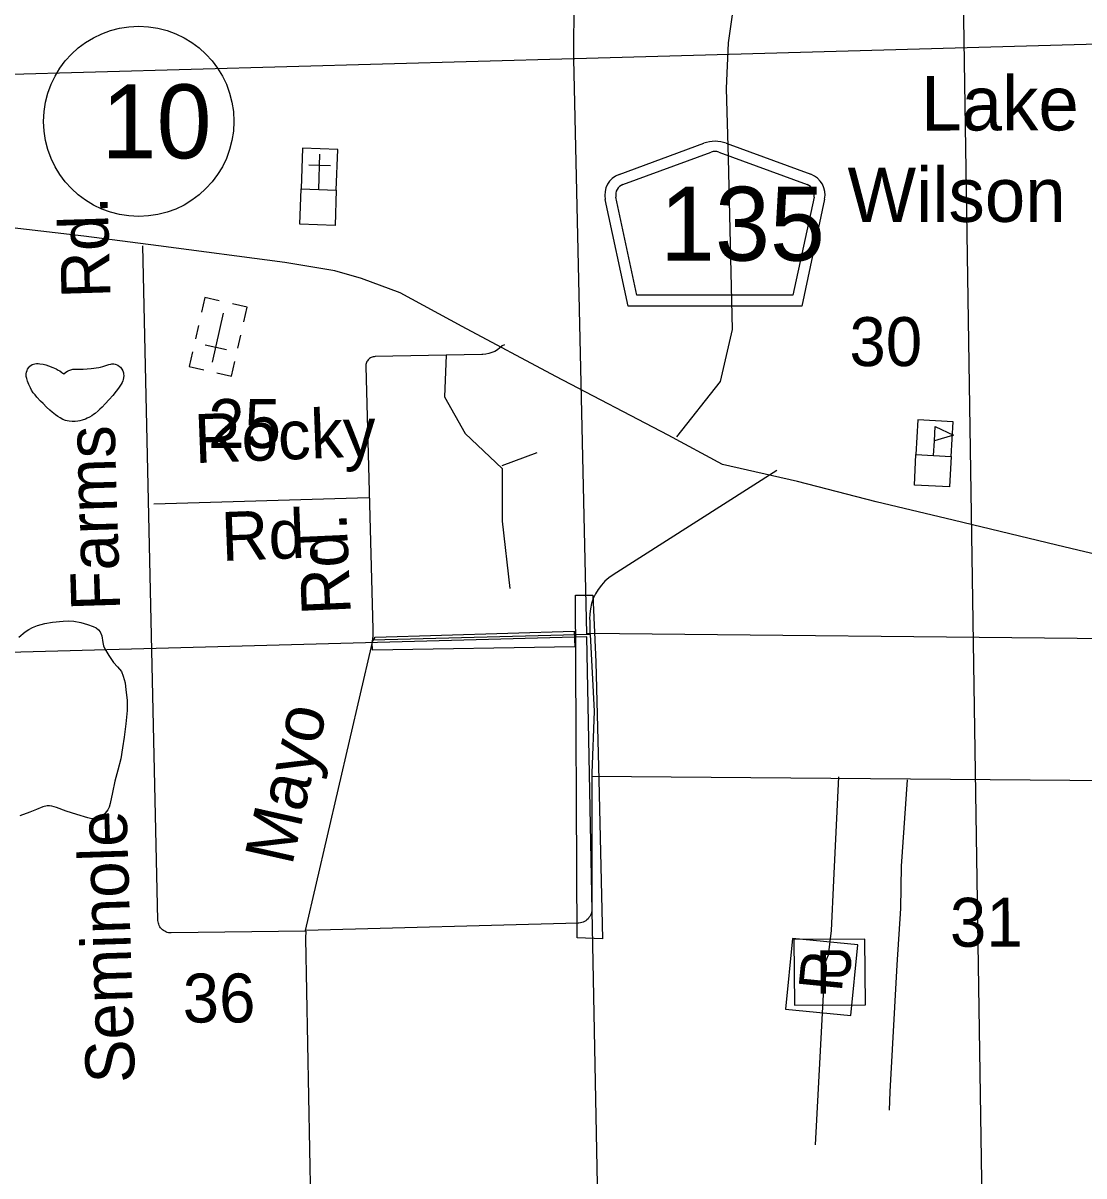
# Model space of a CAD drawing. Extents: x 2480962 to 2688785, y 277103 to 599240.
# Drawn here: x 2512670 to 2522427, y 432313 to 442917 of the extents above; entities that cross this region are included whole.
import ezdxf

# ---------------------------------------------------------------- set-up
doc = ezdxf.new("R2010")
doc.units = 0
for name, color, linetype in [('County Routes Highway Center Lines', 7, 'Continuous'), ('Culture', 7, 'Continuous'), ('Divided_Highway', 7, 'Continuous'), ('Lakes and Ponds', 7, 'Continuous'), ('Lakes and Ponds Text', 7, 'Continuous'), ('Level 31', 7, 'Continuous'), ('Local Roads Improved', 7, 'Continuous'), ('Local Roads Paved', 7, 'Continuous'), ('Local Roads Related Cells', 7, 'Continuous'), ('Local Roads Related Text', 7, 'Continuous'), ('Local Roads Unimproved', 7, 'Continuous'), ('Planning Number US Highways', 7, 'Continuous'), ('Roadshields County Roads', 7, 'Continuous'), ('Section Lines', 7, 'Continuous'), ('Section Numbers', 7, 'Continuous'), ('Swamps', 7, 'Continuous'), ('Township and Range lines', 7, 'Continuous'), ('Uninventoried Roads and Features', 7, 'Continuous'), ('US Routes Highway Center Lines', 7, 'Continuous')]:
    doc.layers.add(name, color=color, linetype=linetype)

msp = doc.modelspace()

# ---------------------------------------------------------------- linework, layer by layer
at = {"layer": 'County Routes Highway Center Lines'}
msp.add_lwpolyline([(2518682.245, 439111.771), (2519083.741, 439621.245), (2519193.643, 440097.485), (2519157.009, 441672.74), (2519138.692, 442313.832), (2519157.009, 442735.121), (2519211.96, 443119.776), (2519193.643, 443962.354), (2519138.692, 445995.532), (2519073.011, 448489.411)], dxfattribs=at)
at = {"layer": 'Culture'}
for p, q in [((2515239.693, 441766.048), (2515226.194, 441391.29)), ((2515564.483, 441754.348), (2515239.693, 441766.048)), ((2515388.589, 441385.441), (2515400.294, 441710.378)), ((2515550.984, 441379.591), (2515564.483, 441754.348)), ((2515296.753, 441613.895), (2515496.767, 441606.69)), ((2515226.194, 441391.29), (2515550.984, 441379.591)), ((2514340.685, 440391.106), (2514310.341, 440256.993)), ((2514474.798, 440360.762), (2514340.685, 440391.106)), ((2514730.831, 440302.832), (2514596.718, 440333.177)), ((2514700.487, 440168.719), (2514730.831, 440302.832)), ((2514411.623, 439798.325), (2514513.69, 440249.433)), ((2514282.755, 440135.072), (2514255.169, 440013.151)), ((2514645.317, 439924.878), (2514672.903, 440046.799)), ((2514227.584, 439891.23), (2514197.239, 439757.117)), ((2514539.505, 439910.37), (2514344.431, 439954.506)), ((2514197.239, 439757.117), (2514331.353, 439726.773)), ((2514587.387, 439668.843), (2514617.731, 439802.956)), ((2514453.275, 439699.188), (2514587.387, 439668.843)), ((2520898.682, 439266.148), (2520881.956, 438947.001)), ((2521222.92, 439249.155), (2520898.682, 439266.148)), ((2521206.194, 438930.008), (2521222.92, 439249.155)), ((2521044.076, 438938.505), (2521051.161, 439073.696)), ((2520881.956, 438947.001), (2521206.194, 438930.008))]:
    msp.add_line(p, q, dxfattribs=at)
for points in [[(2515226.194, 441391.29), (2515550.984, 441379.591), (2515539.284, 441054.801), (2515214.495, 441066.501)], [(2521058.064, 439205.421), (2521226.602, 439125.466), (2521051.161, 439073.696)], [(2520881.956, 438947.001), (2521206.194, 438930.008), (2521191.509, 438649.792), (2520867.27, 438666.785)]]:
    msp.add_lwpolyline(points, close=True, dxfattribs=at)
at = {"layer": 'Divided_Highway'}
msp.add_line((2521075.087, 458914.627), (2521773.243, 413460.785), dxfattribs=at)
at = {"layer": 'Lakes and Ponds'}
for points in [[(2513044.214, 439690.458), (2513063.922, 439705.072), (2513079.213, 439714.743), (2513091.036, 439720.988), (2513109.447, 439728.311), (2513128.8, 439732.648), (2513152.551, 439734.06), (2513188.273, 439732.615), (2513206.113, 439732.033), (2513223.898, 439732.614), (2513295.589, 439739.468), (2513366.564, 439748.395), (2513380.588, 439751.001), (2513404.949, 439757.811), (2513441.246, 439770.163), (2513459.377, 439775.76), (2513477.553, 439780.021), (2513487.428, 439781.388), (2513504.767, 439781.412), (2513517.795, 439779.201), (2513527.565, 439776.148), (2513542.196, 439769.118), (2513556.773, 439758.883), (2513565.942, 439750.415), (2513573.3, 439741.866), (2513579.155, 439733.386), (2513587.546, 439716.493), (2513592.292, 439700.926), (2513594.6, 439686.934), (2513595.302, 439674.56), (2513593.814, 439653.009), (2513590.64, 439637.271), (2513587.221, 439625.898), (2513580.599, 439609.82), (2513572.408, 439595.277), (2513547.508, 439558.687), (2513527.608, 439531.586), (2513495.715, 439491.66), (2513461.272, 439452.825), (2513424.74, 439413.089), (2513397.923, 439384.575), (2513377.007, 439363.88), (2513360.392, 439348.733), (2513333.26, 439326.589), (2513318.427, 439315.769), (2513302.582, 439305.112), (2513280.188, 439291.769), (2513260.568, 439281.841), (2513243.384, 439274.438), (2513213.282, 439264.227), (2513190.689, 439258.742), (2513173.738, 439255.783), (2513148.309, 439253.102), (2513122.884, 439252.401), (2513095.153, 439254.356), (2513074.334, 439258.212), (2513058.721, 439262.578), (2513035.324, 439271.685), (2513011.98, 439284.105), (2512988.31, 439299.248), (2512969.084, 439312.749), (2512938.055, 439337.022), (2512916.341, 439355.841), (2512885.027, 439385.2), (2512853.657, 439416.098), (2512829.931, 439440.124), (2512796.081, 439476.948), (2512779.834, 439496.228), (2512763.975, 439516.402), (2512747.408, 439541.368), (2512736.937, 439560.93), (2512723.407, 439591.179), (2512711.282, 439621.97), (2512703.457, 439646.194), (2512699.693, 439665.177), (2512698.491, 439679.615), (2512698.685, 439690.447), (2512701.013, 439706.54), (2512706.131, 439722.243), (2512711.041, 439732.136), (2512722.134, 439748.552), (2512731.977, 439759.524), (2512739.898, 439766.664), (2512752.173, 439775.13), (2512764.323, 439780.275), (2512779.401, 439783.31), (2512794.699, 439784.588), (2512809.91, 439784.497), (2512824.808, 439783.357), (2512853.999, 439778.709), (2512880.391, 439772.252), (2512903.717, 439765.023), (2512944.005, 439749.46), (2512972.855, 439735.906), (2512993.207, 439724.991), (2513007.531, 439716.515), (2513027.18, 439703.527), (2513044.214, 439690.458)], [(2512632.299, 437268.8), (2512689.68, 437318.348), (2512721.447, 437339.52), (2512755.849, 437357.923), (2512801.157, 437376.028), (2512870.293, 437393.909), (2512940.824, 437405.354), (2513038.69, 437416.414), (2513087.65, 437418.185), (2513136.316, 437415.84), (2513200.063, 437403.443), (2513263.07, 437384.13), (2513316.041, 437366.688), (2513340.812, 437354.365), (2513363.388, 437336.597), (2513378.071, 437317.83), (2513392.987, 437280.491), (2513403.466, 437219.691), (2513409.936, 437189.963), (2513421.275, 437162.421), (2513459.282, 437098.221), (2513500.356, 437035.733), (2513538.47, 436994.942), (2513557.976, 436974.692), (2513574.209, 436951.268), (2513591.863, 436910.481), (2513607.693, 436847.169), (2513616.252, 436782.373), (2513625.767, 436687.304), (2513627.948, 436639.786), (2513626.569, 436592.382), (2513615.154, 436470.942), (2513599.833, 436349.628), (2513585.47, 436249.049), (2513567.87, 436149.095), (2513542.284, 436045.905), (2513514.767, 435943.294), (2513493.456, 435840.585), (2513472.23, 435737.488), (2513461.374, 435704.241), (2513449.689, 435680.927), (2513425.662, 435649.032), (2513392.829, 435621.412), (2513361.643, 435605.793), (2513337.559, 435599.846), (2513301.278, 435598.839), (2513266.012, 435605.624), (2513165.824, 435637.163), (2513065.334, 435669.025), (2512977.939, 435702.3), (2512934.261, 435714.998), (2512912.576, 435717.578), (2512891.051, 435716.585), (2512851.219, 435706.964), (2512791.941, 435683.197), (2512732.479, 435658.588), (2512640.011, 435626.212)]]:
    msp.add_lwpolyline(points, dxfattribs=at)
at = {"layer": 'Level 31'}
for points in [[(2517749.749, 437654.356), (2517910.612, 437654.356), (2517938.347, 437038.639), (2517966.082, 435956.973), (2517999.364, 434492.564), (2517766.39, 434503.658)], [(2515883.891, 437148.04), (2515880.247, 437220.921), (2515909.399, 437268.293), (2517738.696, 437322.953), (2517745.984, 437180.836)]]:
    msp.add_lwpolyline(points, close=True, dxfattribs=at)
at = {"layer": 'Local Roads Improved'}
for p, q in [((2513910.593, 434664.372), (2513772.684, 440866.869)), ((2517096.492, 439956.317), (2517076.362, 439947.525)), ((2516888.367, 439867.458), (2515907.601, 439848.737)), ((2515821.063, 439758.073), (2515887.383, 437342.88)), ((2519603.647, 438799.922), (2518097.058, 437841.243)), ((2513870.999, 438495.2), (2515849.058, 438554.069)), ((2517881.143, 437428.404), (2517882.877, 437288.254)), ((2515881.869, 437244.091), (2517876.102, 437295.337)), ((2517884.456, 437293.801), (2517921.233, 436587.618)), ((2515871.384, 437183.139), (2515263.157, 434569.481)), ((2517921.233, 436587.618), (2517902.103, 436017.896)), ((2517899.26, 435989.775), (2523531.828, 435942.214)), ((2517902.103, 436017.896), (2517900.811, 434764.644)), ((2515267.764, 434564.551), (2514032.57, 434548.436)), ((2517774.81, 434637.312), (2515271.983, 434569.481)), ((2515268.731, 434495.212), (2515338.41, 430683.222))]:
    msp.add_line(p, q, dxfattribs=at)
for points in [[(2517076.362, 439947.525), (2517055.14, 439928.386), (2517032.033, 439911.571), (2517007.294, 439897.262), (2516981.196, 439885.618), (2516954.023, 439876.765), (2516926.075, 439870.803), (2516897.656, 439867.793), (2516888.367, 439867.458)], [(2515907.601, 439848.737), (2515898.387, 439848.078), (2515889.292, 439846.459), (2515880.416, 439843.897), (2515871.856, 439840.423), (2515863.707, 439836.073), (2515856.057, 439830.895), (2515848.99, 439824.944), (2515842.583, 439818.289), (2515836.908, 439811), (2515832.025, 439803.158), (2515827.989, 439794.848), (2515824.843, 439786.162), (2515822.624, 439777.195), (2515821.353, 439768.045), (2515821.046, 439758.812), (2515821.063, 439758.073)], [(2518097.058, 437841.243), (2518057.542, 437813.522), (2518021.141, 437781.821), (2517988.251, 437746.49), (2517959.236, 437707.915), (2517934.411, 437666.517), (2517914.049, 437622.752), (2517898.373, 437577.098), (2517887.556, 437530.055), (2517881.715, 437482.14), (2517880.914, 437433.876), (2517881.143, 437428.404)], [(2515887.383, 437342.88), (2515885.734, 437276.709), (2515877.178, 437211.071), (2515871.384, 437183.139)], [(2517900.811, 434764.644), (2517899.855, 434751.098), (2517897.488, 434737.727), (2517893.737, 434724.676), (2517888.642, 434712.089), (2517882.259, 434700.104), (2517874.659, 434688.851), (2517865.925, 434678.454), (2517856.151, 434669.028), (2517845.445, 434660.674), (2517833.925, 434653.486), (2517821.717, 434647.541), (2517808.954, 434642.904), (2517795.776, 434639.628), (2517782.328, 434637.747), (2517774.81, 434637.312)], [(2514032.57, 434548.436), (2514020.157, 434548.731), (2514007.843, 434550.322), (2513995.763, 434553.192), (2513984.049, 434557.308), (2513972.83, 434562.627), (2513962.228, 434569.089), (2513952.36, 434576.625), (2513943.333, 434585.15), (2513935.247, 434594.572), (2513928.19, 434604.788), (2513922.24, 434615.685), (2513917.461, 434627.145), (2513913.907, 434639.042), (2513911.615, 434651.245), (2513910.612, 434663.621), (2513910.593, 434664.372)], [(2515271.304, 434562.837), (2515268.663, 434499.965), (2515268.731, 434495.212)]]:
    msp.add_lwpolyline(points, dxfattribs=at)
at = {"layer": 'Local Roads Paved'}
msp.add_line((2517074.652, 438848.401), (2517397.844, 438965.926), dxfattribs=at)
msp.add_lwpolyline([(2516560.482, 439862.051), (2516545.791, 439480.096), (2516736.769, 439142.213), (2517074.652, 438819.02), (2517074.652, 438334.231), (2517148.105, 437717.228)], dxfattribs=at)
at = {"layer": 'Local Roads Related Cells'}
for p, q in [((2519745.727, 434498.139), (2519681.455, 433848.107)), ((2520346.003, 434438.788), (2519745.727, 434498.139)), ((2520412.178, 434491.187), (2519758.995, 434486.239)), ((2519758.995, 434486.239), (2519763.564, 433883.053)), ((2520416.748, 433888.002), (2520412.178, 434491.187)), ((2520281.731, 433788.755), (2520346.003, 434438.788)), ((2519681.455, 433848.107), (2520281.731, 433788.755)), ((2519763.564, 433883.053), (2520416.748, 433888.002))]:
    msp.add_line(p, q, dxfattribs=at)
at = {"layer": 'Local Roads Unimproved'}
for points in [[(2520169.157, 435982.79), (2520124.819, 435029.533), (2520102.65, 434571.379), (2520073.092, 434342.302), (2520043.534, 434268.406), (2519954.859, 432598.359)], [(2520802.178, 435955.924), (2520746.442, 435161.681), (2520739.475, 434771.527), (2520704.64, 434255.966), (2520641.936, 433085.503), (2520634.969, 432918.294)]]:
    msp.add_lwpolyline(points, dxfattribs=at)
at = {"layer": 'Planning Number US Highways'}
msp.add_circle((2513733.469, 442012.56), 875, dxfattribs=at)
at = {"layer": 'Roadshields County Roads'}
for p, q in [((2518151.19, 441524.86), (2518930.565, 441811.197)), ((2519137.478, 441811.197), (2519915.5, 441525.357)), ((2518185.676, 441430.994), (2518999.536, 441730.001)), ((2519068.507, 441730.001), (2519881.015, 441431.49)), ((2518235.162, 440313.034), (2518024.605, 441295.205)), ((2518315.996, 440413.034), (2518122.383, 441316.167)), ((2519944.308, 441316.663), (2519750.588, 440413.034)), ((2520042.086, 441295.703), (2519831.422, 440313.034)), ((2519750.588, 440413.034), (2518315.996, 440413.034)), ((2519831.422, 440313.034), (2518235.162, 440313.034))]:
    msp.add_line(p, q, dxfattribs=at)
for centre, radius, start, end in [((2519034.022, 441529.6), 300, 69.8269806, 110.1730139), ((2519034.021, 441636.135), 100, 69.8269876, 110.1729839), ((2518220.161, 441337.129), 200, 110.1729839, 192.0998896), ((2519846.529, 441337.625), 200, 347.9000917, 69.8270083), ((2518220.161, 441337.129), 100, 110.1729839, 192.0998896), ((2519846.529, 441337.625), 100, 347.9000932, 69.8269876)]:
    msp.add_arc(centre, radius, start, end, dxfattribs=at)
at = {"layer": 'Section Lines'}
for p, q in [((2523064.31, 442736.641), (2517740.051, 442588.935)), ((2517735.821, 442588.815), (2512452.102, 442438.943)), ((2517854.815, 437270.921), (2512536.869, 437128.091)), ((2523642.266, 437244.203), (2517854.229, 437300.461))]:
    msp.add_line(p, q, dxfattribs=at)
at = {"layer": 'Swamps'}
msp.add_line((2517735.821, 442588.815), (2517740.051, 442588.935), dxfattribs=at)
at = {"layer": 'Township and Range lines'}
for p, q in [((2517735.821, 442588.815), (2517739.887, 443816.912)), ((2517854.26, 437299.072), (2517735.821, 442588.815)), ((2517958.938, 431993.946), (2517854.815, 437270.921))]:
    msp.add_line(p, q, dxfattribs=at)
at = {"layer": 'US Routes Highway Center Lines'}
msp.add_lwpolyline([(2523117.326, 437890.798), (2522177.307, 438114.821), (2521224.111, 438343.237), (2520516.9, 438514.548), (2519792.12, 438699.038), (2519102.48, 438857.172), (2518601.722, 439125.121), (2517569.458, 439665.413), (2516708.507, 440126.637), (2516137.467, 440434.119), (2515781.666, 440565.898), (2515535.679, 440636.18), (2515078.848, 440715.247), (2513914.806, 440868.988), (2513229.559, 440956.84), (2511643.826, 441141.33), (2510053.701, 441343.39), (2509241.068, 441444.42), (2508077.026, 441584.984), (2507180.933, 441703.584), (2505630.341, 441883.681), (2504725.464, 442107.704), (2504497.048, 442182.379), (2504439.944, 442221.912)], dxfattribs=at)

# ---------------------------------------------------------------- texts
at = {"layer": 'Lakes and Ponds Text'}
for s, rotation, p in [('Lake', 0.0290083, (2520930.037, 441928.303)), ('Wilson', 0.0290222, (2520252.757, 441087.339))]:
    msp.add_text(s, height=500, rotation=rotation, dxfattribs=at).set_placement(p)
at = {"layer": 'Local Roads Related Cells'}
msp.add_text('P', height=400, rotation=0.4340506, dxfattribs=at).set_placement((2519962.183, 433987.816))
at = {"layer": 'Local Roads Related Text'}
for s, height, rotation, p in [('Rd.', 450, 92.5445139, (2515684.995, 437481.583)), ('Mayo', 450, 77.3439889, (2515143.161, 435158.107)), ('P', 400, 84.3532806, (2520198.597, 433997.354))]:
    msp.add_text(s, height=height, rotation=rotation, dxfattribs=at).set_placement(p)
at = {"layer": 'Planning Number US Highways'}
msp.add_text('10', height=680, dxfattribs=at).set_placement((2513392.213, 441672.562))
at = {"layer": 'Roadshields County Roads'}
msp.add_text('135', height=680, dxfattribs=at).set_placement((2518527.52, 440731.319))
at = {"layer": 'Section Numbers'}
for s, rotation, p in [('30', 359.9796417, (2520269.838, 439761.838)), ('25', 359.9796417, (2514372.225, 439008.621)), ('31', 0.0994889, (2521194.386, 434420.737)), ('36', 0.0995111, (2514138.21, 433723.71))]:
    msp.add_text(s, height=450, rotation=rotation, dxfattribs=at).set_placement(p)
at = {"layer": 'Uninventoried Roads and Features'}
for s, rotation, p in [('Seminole           Farms       Rd.', 91.7780722, (2513699.097, 433171.874)), ('Rocky', 2.2323639, (2514252.537, 438868.565)), ('Rd.', 2.2323694, (2514500.024, 437968.172))]:
    msp.add_text(s, height=450, rotation=rotation, dxfattribs=at).set_placement(p)

doc.saveas('drawing.dxf')
